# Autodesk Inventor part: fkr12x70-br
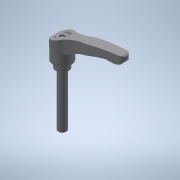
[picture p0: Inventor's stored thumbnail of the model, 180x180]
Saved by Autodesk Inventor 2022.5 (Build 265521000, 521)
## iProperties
Created: 2016-12
Part Number: fkr12x70-br
Material: 一般
Document SubType Name: Modeling
Designer: imaocorp
Density: 1 g/cm^3
Appearance: 既定
Author: imaocorp
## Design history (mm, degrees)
node "fkr12x70-br.x_t1"
node "K1000_412080_012"
node "Base1"
